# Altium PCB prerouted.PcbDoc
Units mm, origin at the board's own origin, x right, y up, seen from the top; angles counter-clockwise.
Board outline 43.18 x 33.02 mm, 2 copper layers (Top Layer, Bottom Layer), stack 0.552 mm thick; 23 components, 25 nets, 105 pads, 0 vias.
Unrouted connection lines stored in the file: 43.
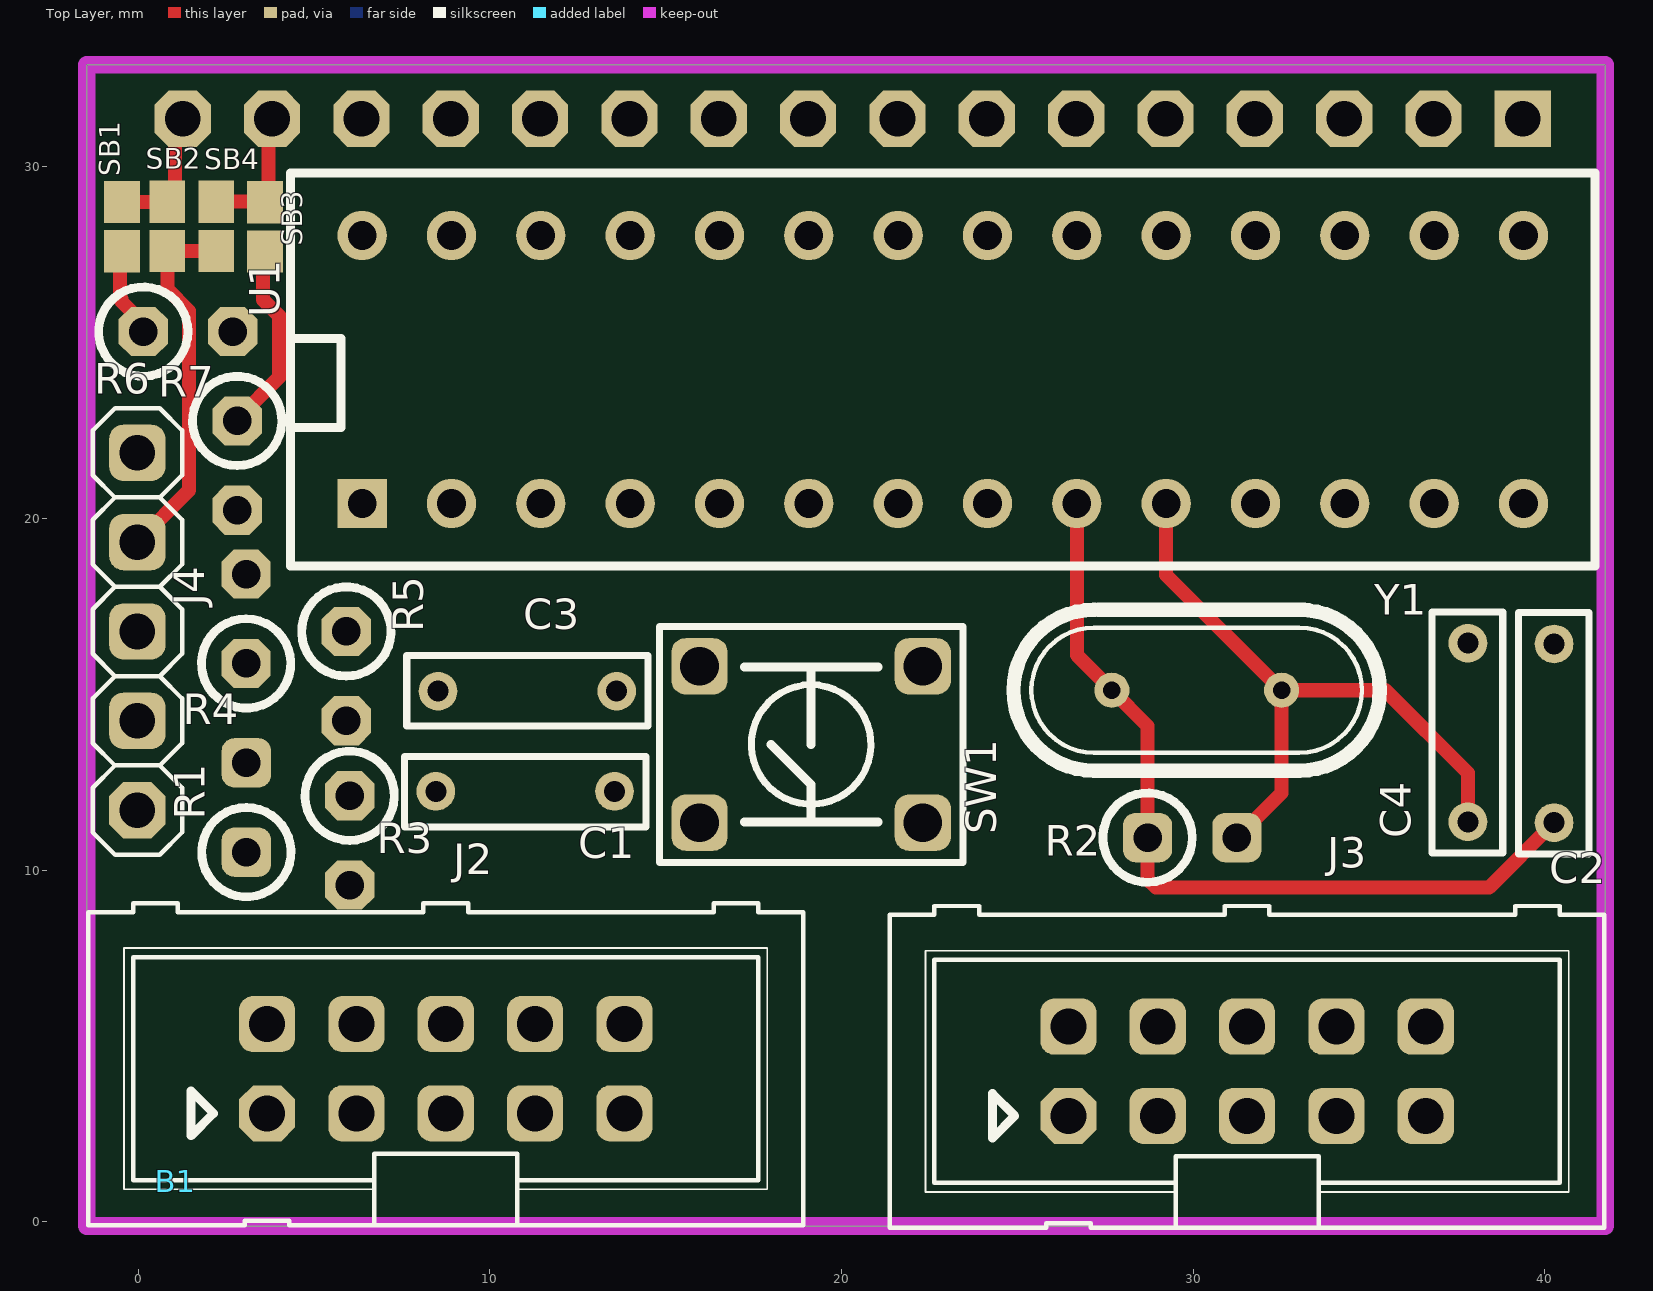
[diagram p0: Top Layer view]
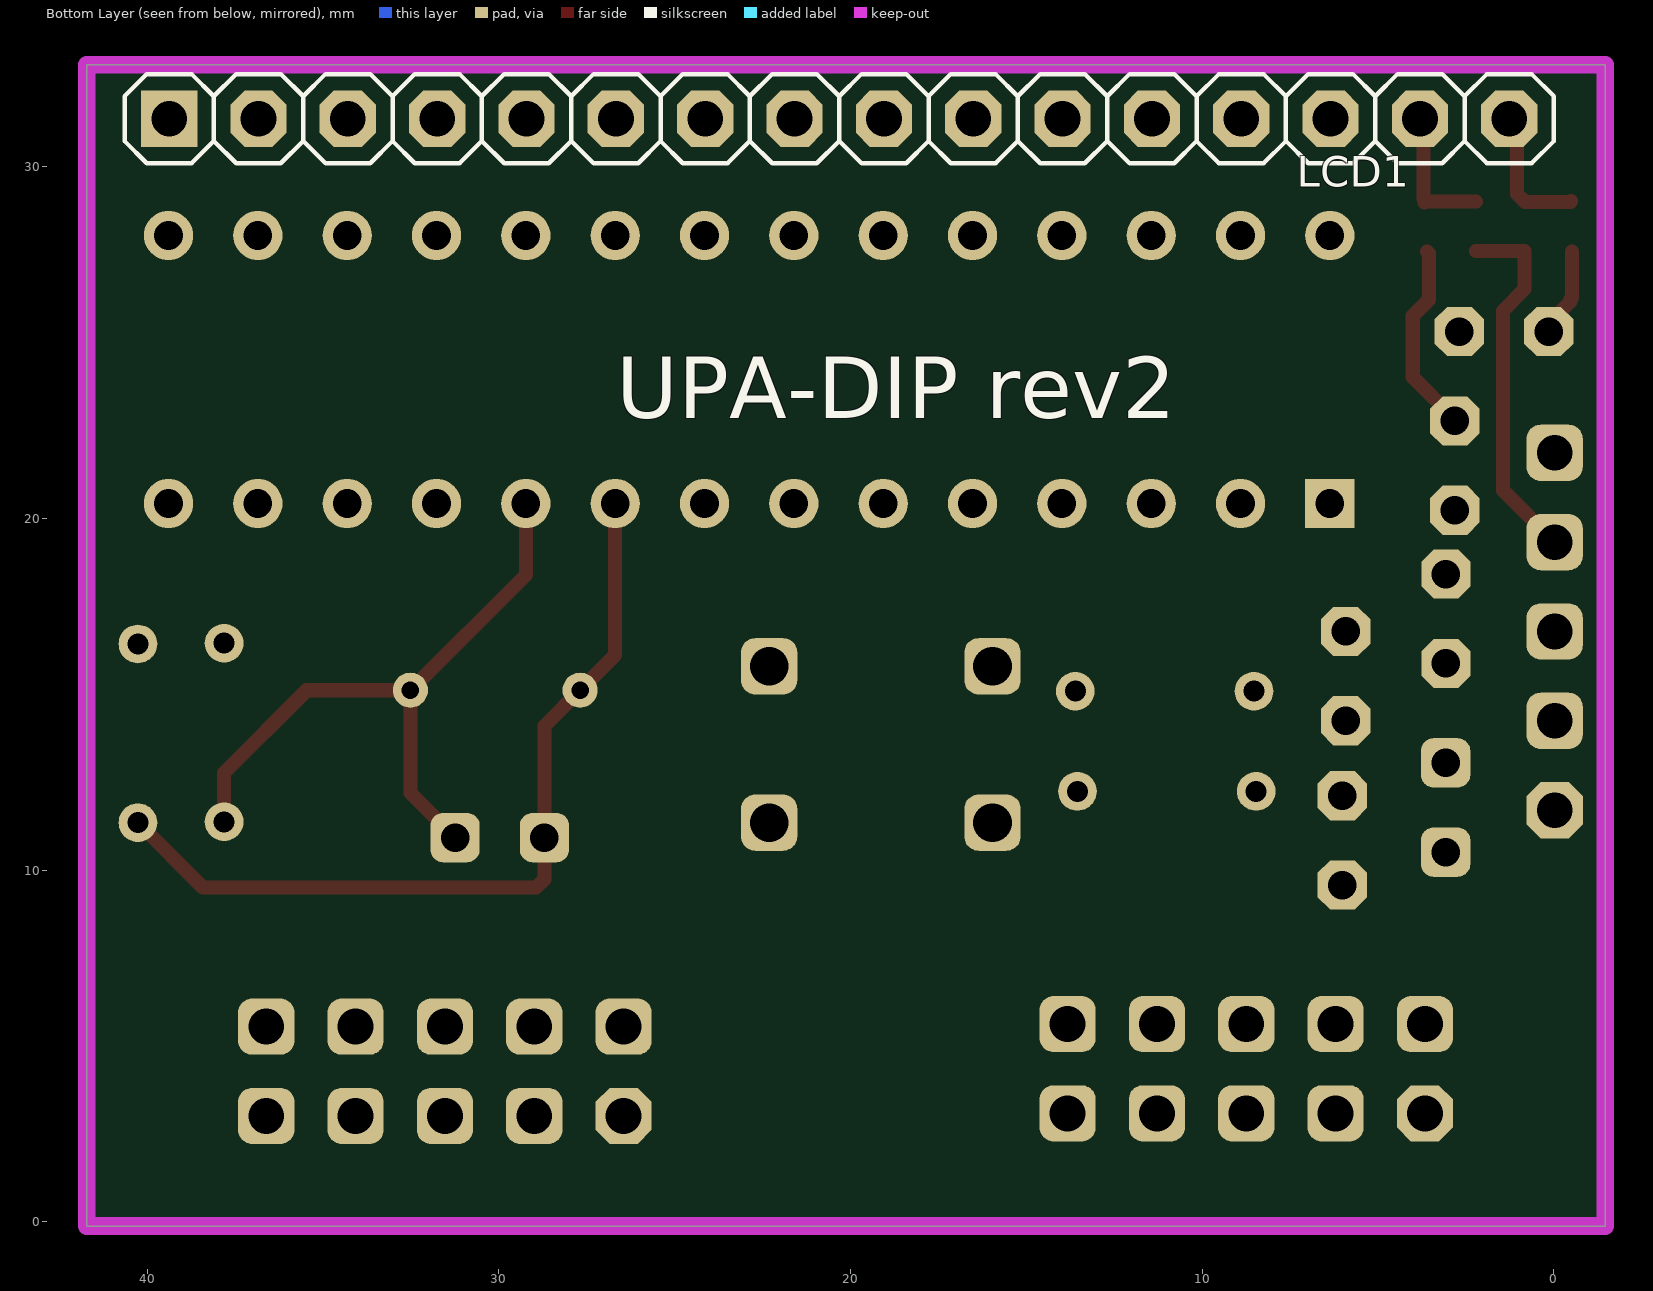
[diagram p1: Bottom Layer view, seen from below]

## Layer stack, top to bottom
Top Solder: solder mask 0.01, Solder Resist, Dk 3.5
Top Layer: signal copper 0.036
Dielectric1: core 0.48, FR-4, Dk 4.8
Bottom Layer: signal copper 0.036
Bottom Solder: solder mask 0.01, Solder Resist, Dk 3.5

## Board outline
-1.463,-0.12 41.717,-0.12 41.717,32.9 -1.463,32.9

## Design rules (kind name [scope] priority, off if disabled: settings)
Clearance "Clearance IN CLASS 1mm" [(InNetClass('CL-1mm'))] p1 off: gap=1 ignorepadtopadclearanceinfootprint=FALSE except(0: Arc-Hole Track-Hole SMDPad-Hole THPad-Hole Via-Hole Fill-Hole Poly-Hole Region-Hole Text-Hole)
Clearance Clearance_GND_PLANE [InNamedPolygon('GND_POLY_TOP')] p2 off: gap=0.4 ignorepadtopadclearanceinfootprint=FALSE except(0: Arc-Hole Track-Hole SMDPad-Hole THPad-Hole Via-Hole Fill-Hole Poly-Hole Region-Hole Text-Hole)
Clearance Clearance_+5V_POLY [InNamedPolygon('poly_+5V-bottom')] p3 off: gap=0.5 ignorepadtopadclearanceinfootprint=FALSE except(0: Arc-Hole Track-Hole SMDPad-Hole THPad-Hole Via-Hole Fill-Hole Poly-Hole Region-Hole Text-Hole)
Clearance [All] p4: gap=0.2 ignorepadtopadclearanceinfootprint=FALSE
ComponentClearance [InComponentClass('N-DAP')] p1: gap=0.2 collisioncheckmode=3 verticalgap=0.2 showdistances=TRUE
MinimumAnnularRing [All] p1: minimumring=0.124
PlaneClearance [All] p1: clearance=0.3
PlaneConnect Plane_ConnectStyle_1 [(Name = 'C1-1') Or (Name = 'C1-2') Or (Name = 'C2-1') Or (Name = 'C2-2') Or (Name = 'C3-1') Or (Name = 'C3-2') Or (Name = 'C4-1') Or (Name = 'C4-2') Or (Name = 'C5-1') Or (Name = 'C5-2') Or (Name = 'C6-1') Or (Name = 'C6-2') Or (Name = 'C7-1')] p1 off: planeconnectstyle=Relief reliefexpansion=1.27 reliefentries=4 reliefconductorwidth=0.381 reliefairgap=0.508
PlaneConnect [All] p2: planeconnectstyle=Direct reliefexpansion=0.635 reliefentries=4 reliefconductorwidth=0.305 reliefairgap=0.254
PolygonConnect [All] p1: connectstyle=Direct reliefconductorwidth=0.254 reliefentries=4 polygonreliefangle="90 Angle" airgapwidth=0.254
RoomDefinition UPA-DIP [InComponentClass('UPA-DIP')] p1: confinementstyle=ConfineIn formatcopy=TRUE lockcomponents=FALSE outline 6.05,48.721 44.785,48.721 44.785,5.541 6.05,5.541
RoutingVias VIASWITDTH2MM [(InNetClass('W-2mm'))] p1 off: holewidth=1 width=1.8 viastyle="Through Hole" minholewidth=0.4 minwidth=0.7 maxholewidth=1 maxwidth=1.8
RoutingVias VIASWITDTH1MM [(InNetClass('W-2mm'))] p2 off: holewidth=0.5 width=1 viastyle="Through Hole" minholewidth=0.5 minwidth=1 maxholewidth=0.5 maxwidth=1
RoutingVias VIASWITDTH1.5MM [(InNetClass('W-2mm'))] p3 off: holewidth=0.9 width=1.4 viastyle="Through Hole" minholewidth=0.9 minwidth=1.4 maxholewidth=0.9 maxwidth=1.4
RoutingVias [All] p4: holewidth=0.3 width=0.7 viastyle="Through Hole" minholewidth=0.2 minwidth=0.5 maxholewidth=4 maxwidth=2
SilkToSolderMaskClearance SilkscreenOverComponentPads [IsPad] p1: minsilkscreentomaskgap=0.254 clearancetoexposedcopper=TRUE
SolderMaskExpansion [All] p1: expansion=0 istentingtop=FALSE
Width POWER-LINES [InNetClass('SUPPLY-LINES')] p1: maxlimit=2 minlimit=0.2 preferedwidth=0.4
Width [All] p2: maxlimit=2 minlimit=0.4 preferedwidth=0.4
26 further rules are at their usual default settings.

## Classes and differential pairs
component class UPA-DIP: B1 C1 C2 C3 C4 J2 J3 J4 LCD1 R1 R2 R3 R4 R5 R6 R7 SW1 U1 Y1

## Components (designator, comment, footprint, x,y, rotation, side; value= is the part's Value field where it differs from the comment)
B1 "N-GMS-NO-PINS" N-GMS-NO-PINS 1.077,1.15 r0 top locked
C1 "100nF" CK05 8.467,12.237 r0 top
C2 "18p" CK05 40.259,16.429 r270 top
C3 "100nF" CK05 13.607,15.087 r180 top
C4 "18p" CK05 37.81,16.451 r270 top
J2 "Header 5X2" ML10 8.747,4.352 r0 top
J3 "Header 5X2" ML10 31.531,4.28 r0 top
J4 "HEADER_5" 1X05 -0.021,16.784 r90 top
LCD1 "LCD MODULE SIL" 1X16-FEMALE 39.37,31.362 r180 bottom
R1 "10K" RS-2,5#1 3.078,11.779 r90 top
R2 "1M" RS-2,5#1 29.972,10.922 r0 top
R3 "10K" RS-2,5#2 6.016,10.844 r270 top
R4 "10K" RS-2,5#2 3.071,17.145 r90 top
R5 "10K" RS-2,5#2 5.92,15.514 r270 top
R6 "1Κ" RS-2,5#2 1.418,25.31 r0 top
R7 "1Κ" RS-2,5#2 2.817,21.5 r270 top
SB1 "Closed" 0603_JUMPER -0.46,28.292 r90 top
SB2 "Open" 0603_JUMPER 0.83,28.303 r90 top
SB3 "Open" 0603_JUMPER 3.607,28.29 r90 top
SB4 "Closed" 0603_JUMPER 2.219,28.303 r90 top
SW1 "EVQ-P2202M" BUTTON_6X6mm 19.137,13.571 r90 top
U1 "ATmega328PU" DIL28-300WSOCKET 6.37,20.422 r0 top
Y1 "16MHz" HC49U-V 30.107,15.104 r0 top

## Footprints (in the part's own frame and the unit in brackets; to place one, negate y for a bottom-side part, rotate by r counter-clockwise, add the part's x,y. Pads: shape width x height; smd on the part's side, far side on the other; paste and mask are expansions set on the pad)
1X05 [mil]
  oct 63x63 hole 40: 1(-200,0)
  rrect50% 63x63 hole 40: 2(-100,0) 3(0,0) 4(100,0) 5(200,0)
  silkscreen extent -250,-50 250,50
1X16-FEMALE [mil]
  rect 63x63 hole 40: 1(0,0)
  oct 63x63 hole 40: 2(100,0) 3(200,0) 4(300,0) 5(400,0) 6(500,0) 7(600,0) 8(700,0) 9(800,0) 10(900,0) 11(1000,0) 12(1100,0) 13(1200,0) 14(1300,0) 15(1400,0) 16(1500,0)
  silkscreen extent -50,-50 1550,50, body extent -55,-49 1555,49, height 335
0603_JUMPER [mm] "Jumper"
  rect 1.2x1.016 smd: 1(0.7,0) 2(-0.7,-0.003)
BUTTON_6X6mm [mm] "TACTILE BUTTON 6x6mm"
  rrect50% 1.6x1.6 hole 1.1: 1(-2.222,3.175) 2(2.223,3.175) 3(-2.222,-3.175) 4(2.223,-3.175)
  silkscreen extent -3.35,-4.32 3.35,4.32, body extent -3.1,-3.91 3.1,3.99, height 7
CK05 [mm]
  round 1.1 hole 0.6: 1(0,0) 2(5.08,0)
  silkscreen extent -0.89,-1.02 5.97,0.99, body extent -0.25,-1.01 5.33,0.99, height 6
DIL28-300WSOCKET [mm]
  rect 1.4x1.4 hole 0.813: 1(0,0)
  round 1.4 hole 0.813: 2(2.54,0) 3(5.08,0) 4(7.62,0) 5(10.16,0) 6(12.7,0) 7(15.24,0) 8(17.78,0) 9(20.32,0) 10(22.86,0) 11(25.4,0) 12(27.94,0) 13(30.48,0) 14(33.02,0) 15(33.02,7.62) 16(30.48,7.62) 17(27.94,7.62) 18(25.4,7.62) 19(22.86,7.62) 20(20.32,7.62) 21(17.78,7.62) 22(15.24,7.62) 23(12.7,7.62) 24(10.16,7.62) 25(7.62,7.62) 26(5.08,7.62) 27(2.54,7.62) 28(0,7.62)
  silkscreen extent -2.03,-1.78 35.05,9.4, body extent -1.71,-1.24 34.29,8.86, height 9.08
HC49U-V [mm]
  round 1 hole 0.5: 1(-2.421,0.009) 2(2.405,0.009)
  silkscreen extent -5.21,-2.28 5.2,2.3, body extent -5.68,-2.31 5.68,2.34, height 3.8
ML10 [mil]
  oct 63x63 hole 40.16: 1(-200,-50)
  rrect50% 63x63 hole 40.16: 2(-200,50) 3(-100,-50) 4(-100,50) 5(0,-50) 6(0,50) 7(100,-50) 8(100,50) 9(200,-50) 10(200,50)
  silkscreen extent -400,-175 400,185, body extent -400,-175 400,185, height 371
N-GMS-NO-PINS [mm]
RS-2,5#1 [mm]
  rrect50% 1.4x1.4 hole 0.813: 1(-1.27,0) 2(1.27,0)
  silkscreen extent -2.54,-1.27 0,1.27, body extent -2.19,-0.92 1.52,0.92, height 6.75
RS-2,5#2 [mm]
  oct 1.4x1.4 hole 0.813: 1(-1.27,0) 2(1.27,0)
  silkscreen extent -2.54,-1.27 0,1.27, body extent -2.19,-0.92 1.52,0.92, height 6.75

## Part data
C1 C3: library part C, "CAPACITOR", Supplier Part Number 1=594-K104K15X7RF53H5
C2 C4: library part C, "CAPACITOR"
J2 J3: "Header, 5-Pin, Dual row", Supplier Part Number 1=517-30310-6002
LCD1: library part "LCD MODULE SIL_1", "LCD MODULE SINGLE IN LINE"
R1 R3 R4 R5 R6 R7: library part R, "RESISTOR", Supplier Part Number 1=594-SFR25H0001002JR5
R2: library part R, "RESISTOR"
SB1 SB2 SB3 SB4: library part HEADER2_CIRCUIT_BRAKER, "Circuit Breaker"
SW1: library part BUTTON_TACT, "BUTTON TACTILE", Supplier Part Number 1=667-EVQ-P2202M
U1: library part ATmega48/88/168, "8-Bit AVR Microcontroller with 32K Bytes of In-System Programmable Flash Memory"
Y1: library part XTAL, "CRYSTAL"

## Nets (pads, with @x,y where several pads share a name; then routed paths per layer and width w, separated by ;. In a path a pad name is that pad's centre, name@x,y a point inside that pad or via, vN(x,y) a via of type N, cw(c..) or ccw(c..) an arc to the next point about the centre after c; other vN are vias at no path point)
+5V: J3.1 J4.5 LCD1.2 R1.1 R3.1 R4.1 R5.1 R6.2 R7.2 U1.7 U1.20
A2: J4.3 R5.2 U1.25
D2: J4.1 R3.2 U1.4
D3: J4.2 R4.2 U1.5
D4: J2.3 U1.6
D10: J3.5 U1.16
D11: J2.5 U1.17
D12: J2.10 U1.18
D13: J2.9 U1.19
GND: C1.2 C2.1 C3.2 C4.1 J2.2 J3.2 J4.4 LCD1.1 LCD1.3 SB2.2 SB4.2 SW1.2 U1.8 U1.22 | length 11
  Top Layer w0.4: SB2.2 0.833,26.521 1.453,25.901 1.453,20.798 J4.4@0.006,19.352 ; SB2.2@0.899,27.6 2.218,27.6 SB4.2 ; J4.4@0.006,19.282 J4.4@0.006,19.352 ; J4.4@0.006,19.282 J4.4@0.006,19.324 ; J4.4@0.006,19.282 J4.4@0.006,19.352 ; J4.4@0.006,19.282 J4.4@0.006,19.352 ; J4.4@0.006,19.282 J4.4@0.006,19.324 ; J4.4@0.006,19.282 J4.4@0.006,19.352 ; J4.4@0.006,19.282 J4.4@0.006,19.352 ; J4.4@0.006,19.282 J4.4@0.006,19.324 ; J4.4@0.006,19.324 J4.4@0.006,19.352 ; J4.4@0.006,19.324 J4.4@0.006,19.352 ; J4.4@0.006,19.324 J4.4@0.006,19.352 ; J4.4@0.006,19.324 J4.4@0.006,19.352
LCD-D4: LCD1.11 U1.11
LCD-D5: LCD1.12 U1.12
LCD-D6: LCD1.13 U1.13
LCD-D7: LCD1.14 U1.14
LCD-EN: LCD1.6 U1.24
LCD-RS: LCD1.4 U1.15
LCD-RW: LCD1.5 U1.23
NetC2_2: C2.2 R2.1 U1.9 Y1.1 | length 23.9
  Top Layer w0.4: U1.9 26.69,16.109 Y1.1 28.702,14.097 R2.1 28.702,9.739 28.936,9.505 38.415,9.505 C2.2
NetC3_1: C3.1 U1.21
NetC4_2: C4.2 R2.2 U1.10 Y1.2 | length 19
  Top Layer w0.4: U1.10 29.23,18.395 Y1.2 ; R2.2 32.512,12.192 Y1.2 ; C4.2 37.81,12.762 35.459,15.113 Y1.2
NetLCD1_15: LCD1.15 SB3.1 SB4.1 | length 24
  Top Layer w0.4: SB3.1@3.683,28.975 3.655,29.003 SB3.1@3.62,29.003 ; LCD1.15@3.732,31.627 LCD1.15@3.709,31.604 ; LCD1.15@3.81,31.079 LCD1.15 ; SB4.1 SB3.1@3.62,29.003 ; SB4.1 SB3.1@3.62,29.003 ; SB4.1 SB3.1@3.62,29.003 ; SB4.1 SB3.1@3.62,29.003 ; SB4.1 SB3.1@3.62,29.003 ; SB4.1 3.607,29.003 SB3.1@3.62,29.003 ; SB3.1@3.62,29.003 SB3.1@3.709,29.092 ; SB3.1@3.709,29.092 LCD1.15@3.709,31.604 ; SB3.1@3.709,29.092 LCD1.15@3.709,31.604 ; SB3.1@3.709,29.092 LCD1.15@3.709,31.604 ; SB3.1@3.709,29.092 LCD1.15@3.709,31.604 ; SB3.1@3.709,29.092 LCD1.15@3.709,31.604 ; SB3.1@3.709,29.092 3.709,31.362 LCD1.15@3.709,31.604
NetLCD1_16: LCD1.16 SB1.1 SB2.1 | length 9.6
  Top Layer w0.4: SB1.1@-0.482,29.017 SB1.1@-0.476,29.011 ; SB1.1@-0.488,29.023 SB1.1@-0.476,29.011 ; SB1.1@-0.488,29.023 SB1.1@-0.476,29.011 ; SB1.1@-0.488,29.023 SB1.1@-0.476,29.011 ; SB1.1@-0.476,28.999 SB2.1@0.826,28.999 ; SB1.1@-0.476,28.999 SB2.1@0.826,28.999 ; SB1.1@-0.476,28.999 SB2.1@0.826,28.999 ; SB1.1@-0.476,28.999 -0.46,28.999 SB2.1@0.826,28.999 ; SB1.1@-0.476,28.999 SB1.1@-0.476,29.011 ; SB2.1@0.826,28.999 SB2.1 1.05,29.223 LCD1.16@1.05,31.284 ; LCD1.16@1.05,31.284 LCD1.16@1.248,31.482 ; LCD1.16@1.05,31.284 LCD1.16@1.199,31.433 ; LCD1.16@1.05,31.284 LCD1.16@1.199,31.433 ; LCD1.16@1.05,31.284 LCD1.16@1.199,31.433 ; LCD1.16@1.05,31.284 LCD1.16@1.199,31.433 ; LCD1.16@1.05,31.284 LCD1.16@1.199,31.433 ; LCD1.16@1.199,31.433 LCD1.16@1.248,31.482 ; LCD1.16@1.199,31.433 LCD1.16@1.248,31.482 ; LCD1.16@1.199,31.433 LCD1.16@1.248,31.482 ; LCD1.16@1.199,31.433 LCD1.16@1.248,31.482 ; LCD1.16@1.199,31.433 LCD1.16@1.248,31.482 ; LCD1.16@1.199,31.433 LCD1.16@1.248,31.482 ; LCD1.16@1.199,31.433 LCD1.16@1.248,31.482 ; LCD1.16@1.199,31.433 LCD1.16@1.248,31.482 ; LCD1.16@1.199,31.433 LCD1.16@1.248,31.482
NetR6_1: R6.1 SB1.2 | length 4.6
  Top Layer w0.4: SB1.2@-0.511,27.585 -0.511,26.273 -0.476,26.238 -0.476,26.167 R6.1@0.055,25.636 ; R6.1 R6.1@0.148,25.543 ; R6.1@0.055,25.274 R6.1@0.055,25.636 ; R6.1@0.055,25.274 R6.1@0.055,25.636 ; R6.1@0.055,25.274 R6.1@0.055,25.636 ; R6.1@0.055,25.274 R6.1@0.055,25.636 ; R6.1@0.055,25.274 R6.1@0.055,25.636 ; R6.1@0.055,25.274 0.055,25.31 R6.1@0.055,25.636
NetR7_1: R7.1 SB3.2 | length 5.5
  Top Layer w0.4: R7.1@2.852,22.802 2.864,22.79 2.864,22.873 4.014,24.023 4.014,25.753 3.551,26.216 3.551,27.532 SB3.2
RESET: C1.1 R1.2 SW1.1 U1.1
pads on no net: J2.1 J2.4 J2.6 J2.7 J2.8 J3.3 J3.4 J3.6 J3.7 J3.8 J3.9 J3.10 LCD1.7 LCD1.8 LCD1.9 LCD1.10 SW1.3 SW1.4 U1.2 U1.3 U1.26 U1.27 U1.28

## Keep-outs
Keep-Out Layer:
  the board outline again, w0.5

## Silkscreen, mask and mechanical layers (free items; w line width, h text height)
Bottom Overlay:
  text "UPA-DIP rev2" at 26.653,22.265 h3
Mechanical 2:
  lines w0.2: 213.504,98.427 213.549,98.472
Mechanical 3:
  the board outline again, w0.25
